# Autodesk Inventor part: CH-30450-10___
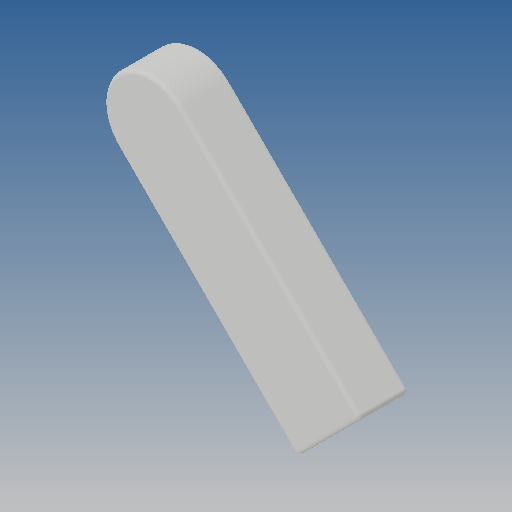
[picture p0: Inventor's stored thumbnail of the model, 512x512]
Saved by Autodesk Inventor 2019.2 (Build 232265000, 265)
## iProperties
Created: 2010-06
Part Number: CH-30450-10___
Material: Ogólny
Document SubType Name: Modeling
Designer: CADENGINEERING4
Density: 1 g/cm^3
Appearance: Domyślna
Author: CADENGINEERING4
Revision Number: ANY
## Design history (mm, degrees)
feature "NONE"
node "Bryła1"
